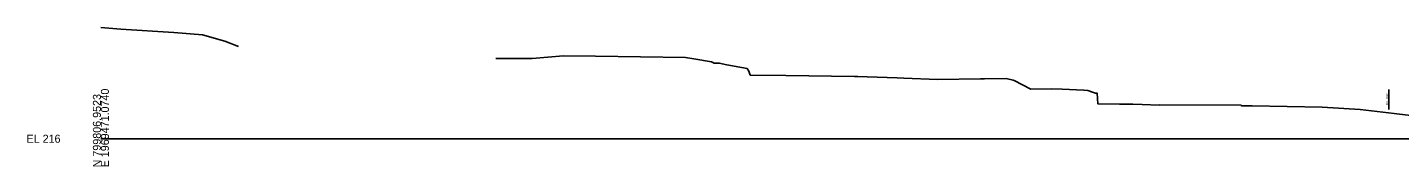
# Model space of a CAD drawing. Extents: x 1979833 to 1982361, y 790388 to 810009.
# Drawn here: x 1981332.9 to 1981812.8, y 794388 to 794436.5 of the extents above; entities that cross this region are included whole.
import ezdxf

# ---------------------------------------------------------------- set-up
doc = ezdxf.new("R2010")
doc.units = 0
for name, color, linetype in [('Default', 7, 'Continuous'), ('RD_GPK_XS_Cell', 7, 'Continuous'), ('RD_XS_ExGround', 7, 'Continuous'), ('RD_XS_ExRW', 7, 'Continuous')]:
    doc.layers.add(name, color=color, linetype=linetype)

msp = doc.modelspace()

# ---------------------------------------------------------------- linework, layer by layer
at = {"layer": 'RD_GPK_XS_Cell'}
msp.add_line((1981358.57, 794397.73), (1981858.57, 794397.73), dxfattribs=at)
at = {"layer": 'RD_XS_ExGround'}
for points in [[(1981358.57, 794436.54), (1981365.55, 794436), (1981384.12, 794434.84), (1981394.08, 794434.03), (1981401.87, 794431.73), (1981406.73, 794429.88)], [(1981496.67, 794425.77), (1981509.37, 794425.67), (1981520.4, 794426.69), (1981531.56, 794426.56), (1981563.03, 794426.12), (1981565.94, 794425.66), (1981572.19, 794424.57), (1981573.14, 794424.15), (1981574.86, 794424.13), (1981577.49, 794423.53), (1981584.58, 794422.26), (1981585.21, 794421.27), (1981585.69, 794419.94), (1981598.13, 794419.81), (1981622.13, 794419.45), (1981623.28, 794419.44), (1981626.64, 794419.32), (1981637.05, 794418.95), (1981639.47, 794418.88), (1981651.25, 794418.44), (1981666.21, 794418.6), (1981667.22, 794418.59), (1981667.59, 794418.61), (1981675.19, 794418.77), (1981677.68, 794418.19), (1981678.03, 794418.02), (1981683.88, 794415.08), (1981691.13, 794415.1), (1981694.8, 794414.98), (1981702.36, 794414.66), (1981703.81, 794414.58), (1981705.39, 794414), (1981706.44, 794413.63), (1981707.02, 794413.63), (1981707.26, 794409.94), (1981714.85, 794409.78), (1981719.49, 794409.74), (1981722.74, 794409.71), (1981728.73, 794409.47), (1981728.77, 794409.51), (1981757.37, 794409.41), (1981757.5, 794409.21), (1981758.55, 794409.21), (1981761.29, 794409.15), (1981785.75, 794408.76), (1981799, 794407.89), (1981810.95, 794406.53), (1981812.77, 794406.3), (1981817.8, 794405.75)]]:
    msp.add_lwpolyline(points, dxfattribs=at)
at = {"layer": 'RD_XS_ExRW'}
msp.add_line((1981809.05, 794407.88), (1981809.05, 794414.88), dxfattribs=at)

# ---------------------------------------------------------------- texts
at = {"layer": 'Default'}
msp.add_text('-', height=0.0001, dxfattribs=at).set_placement((1981358.57, 794397.73))
msp.add_text('-', height=0.0001, dxfattribs=at).set_placement((1981358.57, 794397.73))
at = {"layer": 'RD_GPK_XS_Cell'}
for s, p in [('N 799806.9523', (1981358.57, 794387.73)), ('E 1969471.0740', (1981361.37, 794387.73))]:
    msp.add_text(s, height=2.8, rotation=90, dxfattribs=at).set_placement(p)
msp.add_text('EL 216', height=2.8, dxfattribs=at).set_placement((1981332.57, 794396.33))
at = {"layer": 'RD_XS_ExRW'}
msp.add_text('EX. R/W ', height=0.75, rotation=90, dxfattribs=at).set_placement((1981808.8, 794409.56))

doc.saveas('drawing.dxf')
